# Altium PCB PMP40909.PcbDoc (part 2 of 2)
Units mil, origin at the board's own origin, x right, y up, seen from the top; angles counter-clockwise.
Board outline 3960.53 x 2185.03 mil, 4 copper layers (Top Layer, Signal Layer 1, Signal Layer 2, Bottom Layer), stack 45.434 mil thick; 68 components, 27 nets, 148 pads, 352 vias.
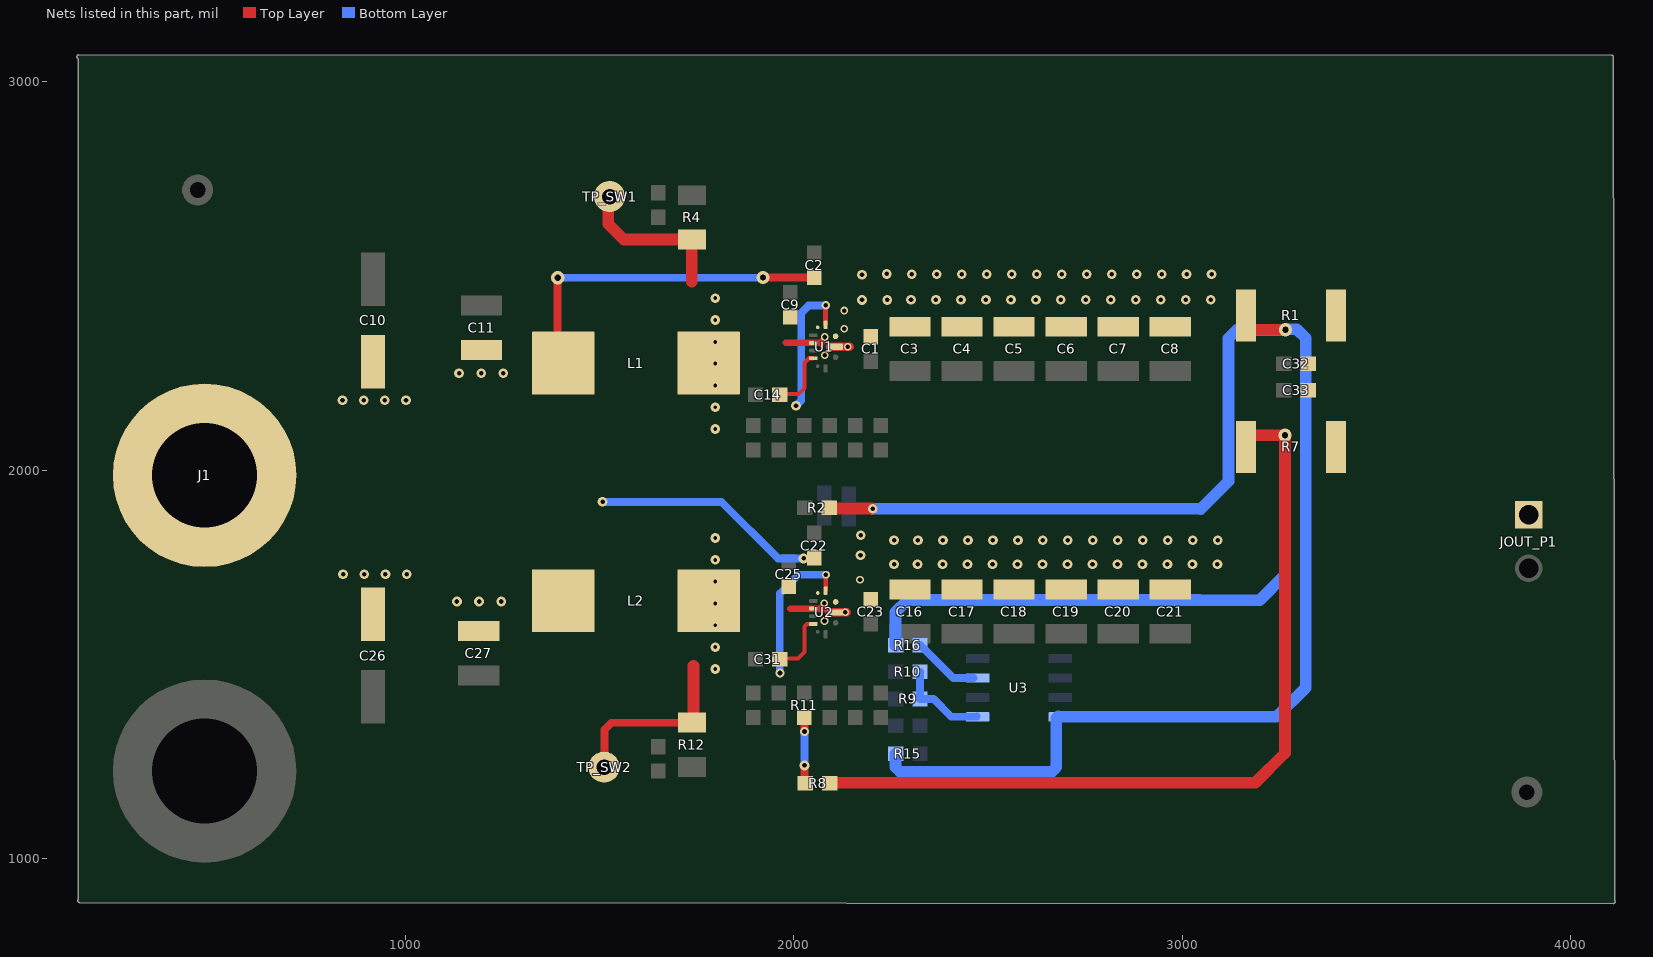
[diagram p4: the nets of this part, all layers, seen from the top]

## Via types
v1: diameter 25, hole 11.81, Top Layer to Bottom Layer, tented both sides, 205 vias
v2: diameter 25, hole 11.81, Top Layer to Bottom Layer, 100 vias
v3: diameter 20, hole 11.81, Top Layer to Bottom Layer, tented both sides, 14 vias
v4: diameter 25, hole 10, Top Layer to Bottom Layer, 14 vias
v5: diameter 20, hole 11.81, Top Layer to Bottom Layer, 4 vias
v6: diameter 23.62, hole 11.81, Top Layer to Bottom Layer, tented both sides, 3 vias
v7: diameter 34, hole 16, Top Layer to Bottom Layer, tented both sides, 3 vias
v8: diameter 34, hole 16, Top Layer to Bottom Layer, 2 vias
v9: diameter 19.68, hole 11.81, Top Layer to Bottom Layer, tented both sides, 2 vias
v10: diameter 23.62, hole 13.78, Top Layer to Bottom Layer, tented both sides, 1 vias
v11: diameter 20, hole 10, Top Layer to Bottom Layer, tented both sides, 1 vias
v12: diameter 20, hole 10, Top Layer to Bottom Layer, 1 vias
v13: diameter 19.68, hole 11.81, Top Layer to Bottom Layer, 1 vias
v14: diameter 22, hole 11.81, Top Layer to Bottom Layer, tented both sides, 1 vias

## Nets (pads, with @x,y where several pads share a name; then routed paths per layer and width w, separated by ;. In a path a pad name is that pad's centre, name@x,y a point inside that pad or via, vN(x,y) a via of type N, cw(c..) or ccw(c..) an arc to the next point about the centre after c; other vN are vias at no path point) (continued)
NetR8_2: R8.2 R11.1 | length 182.7
  Top Layer w15: R11.1@2029,1360.5 R11.1@2030,1361.5
  Top Layer w20: R8.2@2027,1188 2028,1189 v1(2028,1240) v1@2028.5,1239.5 ; v6(2028,1327.5) 2028,1359.5 R11.1@2029,1360.5
  Bottom Layer w15: v1(2028,1240) 2028,1237.5 2027.5,1237 v1@2029,1235.5 ; v6(2028,1327.5) 2028,1328 v6@2029,1329
  Bottom Layer w20: v1(2028,1240) v6(2028,1327.5)
NetR9_2: R9.2 R10.1 U3.1 | length 235.2
  Bottom Layer w20: R10.1@2325.5,1481 R9.2@2325.5,1411.09 2360.32,1411.09 2406.1,1365.3 2470.8,1365.3 U3.1@2471.5,1366
NetR16_2: R16.2 U3.3 | length 172.8
  Bottom Layer w20: R16.2@2325.5,1550 2326,1550 2410.7,1465.3 U3.3@2463.2,1465.3
SW1: C9.1 L1.2 R4.1 TP_SW1.1 U1.4 U1.9 | length 611.4
  Top Layer w5: 2062,2329 2071,2338 ; 2063,2326 2072,2317 ; 2088,2332 U1.4@2097,2323 ; 2089,2305 U1.4@2098,2314
  Top Layer w17: 1979.16,2327.84 U1.9@2050.74,2327.84 2072.16,2327.84
  Top Layer w20: U1.4@2092,2318 U1.4@2106.84,2318
  Top Layer w21: U1.4@2100.34,2318 v9@2144.5,2318
  Top Layer w30: TP_SW1.1@1523,2702 1523,2634 1563.09,2593.91 R4.1@1738,2593.91 1738,2485
  other v3: 2080,2296 2080,2343
  other v4: 1798,2106 1798,2162.17 1798,2218.33 1798,2274.5 1798,2330.67 1798,2386.83 1798,2443
  other v9: 2139,2318
SW2: C25.1 L2.2 R12.1 TP_SW2.1 U2.4 U2.9 | length 673.5
  Top Layer w5: 2062,1645 v3@2071,1654 ; 2063,1642 2072,1633 ; 2088,1648 U2.4@2097,1639 ; 2089,1621 U2.4@2098,1630
  Top Layer w10: R12.1@1730,1360 R12.1@1738,1352
  Top Layer w17: 1991.16,1643.84 U2.9@2050.74,1643.84 2076.84,1643.84
  Top Layer w20: TP_SW2.1@1513,1235 1513,1332 1531.09,1350.09 R12.1@1738,1350.09 ; R12.1@1737.01,1351.08 R12.1@1737.04,1351.04 ; U2.4@2091,1634 U2.4@2106.84,1634
  Top Layer w21: U2.4@2097,1634.5 v3@2137.16,1634.5
  Top Layer w30: R12.1@1742,1357 1742,1497
  other v3: 2079.5,1612 2133,1634.5 2079,1657.5
  other v4: 1798,1488.5 1798,1544.67 1798,1600.83 1798,1657 1798,1713.17 1798,1769.33 1798,1825.5
VCC1: C14.2 U1.6 U1.11 | length 528.4
  Top Layer w10: C14.2@1974,2196 2013,2196 2028,2211 ; U1.6@2082,2374.34 U1.6@2082.24,2374.1 ; v14@2082,2423 v14@2085,2426
  Top Layer w11: 2028,2211 2028,2276.91 2039.57,2288.47 U1.11@2050.74,2288.47
  Top Layer w12: U1.6@2082,2374.34 v14@2082,2423
  Bottom Layer w10: v1(2006,2166) v1@2010.5,2166
  Bottom Layer w20: v1(2006,2166) 2019.5,2179.5 2019.5,2405 2038.5,2424 v14@2084,2424
  other v14: 2083,2424.5
VCC2: C31.2 U2.6 U2.11 | length 537.2
  Top Layer w10: C31.2@1977,1515 2011,1515 2028,1532 2028,1597.94 2034.53,1604.47 U2.11@2050.74,1604.47 ; v3@2082.24,1731.24 v3@2083,1732
  Top Layer w12: U2.6@2082.24,1690.1 v3@2082.24,1731.24
  Bottom Layer w20: v10@1964,1476 1964,1682.5 2012.5,1731 v3(2083,1731)
  other v10: 1965,1478
VIN1: C2.2 C10.1 C11.1 C22.2 C26.1 C27.1 J1.1 L1.1 L2.1 U1.7 U2.7 | length 1409.6
  Top Layer w20: L1.1@1392,2352.5 v7@1392,2493 ; v7(1921.38,2496.38) C2.2@2053,2496.38 ; v1@2026,1772 C22.2@2055,1772
  Bottom Layer w20: v7(1392.5,2495.5) 1920.5,2495.5 v7(1921.38,2496.38) v7@1923.5,2498.5 ; v1@1509.5,1918.5 1814,1918.5 1959.5,1773 v1(2025.5,1773)
  other v1: 1133,1662 1190,1662 1247,1662 840,1732.5 894.5,1732.5 949,1732.5 1003.5,1732.5 1508,1919 838.5,2180 893,2180 947.5,2180 1002,2180 1138.5,2250 1195.5,2250 1252.5,2250
VOUT: C32.1 C33.1 JOUT_P1.1 R1.2 R7.2
VOUT1: C1.1 C3.1 C4.1 C5.1 C6.1 C7.1 C8.1 R1.1 R2.2 R15.1 U1.5 U3.8 | length 3912.7
  Top Layer w20: R1.1@3159,2363 R1.1@3160,2362
  Top Layer w30: R2.2@2088,1901.5 v1@2201,1901.5 ; R1.1@3160,2362 v8(3266,2362)
  Bottom Layer w30: v1(2203.5,1901) 3047.5,1901 3048.25,1900.25 3119.5,1971.5 3119.5,2340 3141.5,2362 v8(3266,2362) ; R15.1@2262,1270 2262,1236 2275,1223 2664,1223 2676.46,1235.46 2676.46,1361.96 U3.8@2679.5,1365 ; U3.8@2681,1366.5 U3.8@2679.5,1365 ; v8@3267,2363 3295.5,2363 3318,2340.5 3318,1440 3243,1365 U3.8@2679.5,1365
  other v2: 2176,2438.5 2241,2438.5 2302,2439 2366.33,2439 2430.67,2439 2495,2439 2559.33,2439 2623.67,2439 2688,2439 2752.33,2439 2816.66,2439 2881,2439 2945.33,2439 3009.66,2439 3074,2439 2176,2503.5 2304,2505 2368.33,2505 2432.67,2505 2497,2505 2561.33,2505 2625.67,2505 2690,2505 2754.33,2505 2818.67,2505 2883,2505 2947.33,2505 3011.67,2505 3076,2505 2240,2505.5
  other v5: 2130,2364.5 2130,2411
VOUT2: C16.2 C17.2 C18.2 C19.2 C20.2 C21.2 C23.1 R7.1 R8.1 R16.1 U2.5 | length 3614.9
  Top Layer w20: R7.1@3159,2089 3159.5,2089.5 3161.5,2089.5 R7.1@3160,2091
  Top Layer w30: R8.1@2090.12,1195 2090.62,1195.5 3188.5,1195.5 3265,1272 v8(3265,2090) 3175,2090 R7.1@3171,2094
  Bottom Layer w30: R16.1@2262,1549 2262,1634 2294,1666 3045,1666 ; 3043,1665.5 3200,1665.5 3265,1730.5 v8(3265,2090)
  other v2: 2258.5,1758 2319,1758 2383.33,1758 2447.67,1758 2512,1758 2576.33,1758 2640.67,1758 2705,1758 2769.33,1758 2833.67,1758 2898,1758 2962.33,1758 3026.67,1758 3091,1758 2172.11,1781 2258.5,1820 2320,1820 2384.33,1820 2448.67,1820 2513,1820 2577.33,1820 2641.67,1820 2706,1820 2770.33,1820 2834.67,1820 2899,1820 2963.33,1820 3027.67,1820 3092,1820 2172.5,1833
  other v5: 2170.8,1718.02
pads on no net: U3.5 U3.6 U3.7

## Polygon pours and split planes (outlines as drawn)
GND on Top Layer "Top Layer-GND" (solid, remove dead copper, pour order 220): 162,3056.5 167,3061.5 4108.5,3061.5 4108.5,891 4107.5,892 162,892 162,3059.25 159.75,3061.5
no net on Top Layer "Top Layer-No Net 1" (solid, remove dead copper, pour order 214): 161,3062.5 166,3067.5 4114,3067.5 4114,890 4109.5,885.5 4107,888 168,888 168,3060.5 158.5,3070
VOUT on Top Layer "TOP_LAYER_VOUT_P180" (solid, remove dead copper, pour order 180): 3293.5,2687 4089,2687 4089,1817 3293.5,1817
VOUT2 on Top Layer "TOP_LAYER_VOUT2_P178" (solid, remove dead copper, pour order 178): 2101,1652 2164.5,1652 2164.5,1633.5 3240,1633.5 3240,2153.5 2255.5,2153.5 2255.5,1874 2101,1874
VOUT1 on Top Layer "TOP_LAYER_VOUT1_P172" (solid, remove dead copper, pour order 172): 2104,3045 2103,3044 2103,2385 2097,2385 2096.5,2384.5 2097,2384 2097,2336.5 2098.5,2335.5 2168,2335.5 2168,2312.5 3234,2312.5 3235,2313.5 3235,3045.5 2103.5,3045.5 2103,3045
SW2 on Top Layer "TOP_LAYER_SW2_P168" (solid, remove dead copper, pour order 168): 1650,1872.5 1650.5,1873 1960.5,1873 1960.5,1729.5 2017,1729.5 2017,1669.5 2034.5,1652 2034.5,1635.5 2026.5,1635.5 2000.5,1609.5 2000.5,1590 2000,1589.5 1881,1589.5 1881,1450.5 1880.5,1451 1649,1451 1649,1873
SW1 on Top Layer "TOP_LAYER_SW1_P166" (solid, remove dead copper, pour order 166): 1645.88,2490 1646.88,2489.5 1874.88,2489.5 1874.88,2471 1875.38,2470.5 1875.88,2471 1965,2471 1965,2429 2016,2429 2016,2351.88 2031.38,2336.5 2031.38,2318.5 1998.88,2286 1998.88,2281.5 1874.88,2281.5 1874.88,2066.5 1874.38,2067 1645.88,2067
VIN1 on Top Layer "TOP_LAYER_VIN1_P144" (solid, remove dead copper, pour order 144): 247.5,2369 248.5,2370 1546.5,2370 1546.5,1513.5 1545,1515 176.5,1515 176.5,2370
GND on Bottom Layer "Bottom Layer-GND" (solid, remove dead copper, pour order 202): 163,3067 167.5,3062.5 4099.5,3062.5 4099.5,903 4109.5,893 156.5,893 158.5,895 158.5,3071
GND on Signal Layer 2 "Signal Layer 2-GND" (solid, remove dead copper, pour order 218): 175.5,3054.5 4102,3054.5 4102,893 4103,892 162,892 162,3057 167.5,3062.5
VOUT on Signal Layer 2 "SIGNAL_LAYER_2_VOUT_P146" (solid, remove dead copper, pour order 146): 3298,2686 4082.5,2686 4082.5,1815.5 3796.5,1815.5 3298,1815.5
VIN1 on Signal Layer 2 "SIGNAL_LAYER_2_VIN1_P142" (solid, remove dead copper, pour order 142): 217,2369 247.5,2369 1546.5,2369 1546.5,1514 1543.5,1511 1540.5,1514 185,1514 185,2367.5
SW1 on Signal Layer 2 "SIGNAL_LAYER_2_SW1_P138" (solid, remove dead copper, pour order 138): 1649,2473 1649.5,2473.5 2097,2473.5 2097,2351 2096.5,2350.5 2107.5,2339.5 2174,2339.5 2175,2338.5 2175,2297 2174.5,2297.5 2107.5,2297.5 2094.5,2284.5 2094.5,2070 1647.5,2070 1648,2070.5 1648,2473.5
VOUT2 on Signal Layer 2 "SIGNAL_LAYER_2_VOUT2_P136" (solid, remove dead copper, pour order 136): 2100.5,1861.5 2234.5,1861.5 2234.5,2153.5 3230.5,2153.5 3230.5,1641 2173,1641 2172,1642 2172,1657.5 2117,1657.5 2100.5,1674 2100.5,1860.5 2101,1861
SW2 on Signal Layer 2 "SIGNAL_LAYER_2_SW2_P140" (solid, remove dead copper, pour order 140): 1649.5,1871 2090,1871 2093,1868 2093,1666 2105,1654 2156,1654 2156,1611 2102,1611 2085,1594 2085,1446 2084.5,1445.5 2082.5,1447.5 1649.5,1447.5
VOUT1 on Signal Layer 2 "SIGNAL_LAYER_2_VOUT1_P134" (solid, pour order 134): 2114.7,3051 3234.5,3051 3234.5,2321.5 3233.5,2320.5 2179,2320.5 2179.5,2321 2179.5,2351.5 2104.5,2351.5 2103,2353 2103.5,2353.5 2103.5,3037
GND on Signal Layer 1 "Signal Layer 1-GND" (solid, pour order 198): 157.5,3066.5 160,3069 4101,3069 4108.5,3061.5 4108.5,902 4101,894.5 162,894.5 162,3056.5

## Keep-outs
Keep-Out Layer:
  text ".Layer_Name" at 577,-858.49 h60

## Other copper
Top Layer:
  rectangle net VOUT2: 2066.5,1175.5 2074.5,1212.5
  rectangle net VOUT1: 2065.5,1884.5 2072,1921.5
  rectangle net AGND2: 2204,1258.5 2245.5,1381.5
  rectangle net VCC2: 1932.5,1453.5 2033,1534.5
  rectangle net VCC1: 1940.5,2142.5 2035,2227.5
  rectangle net VIN1: 2041,2369 2066,2507
  rectangle net VIN1: 2041,1680 2067,1774
  rectangle net SW1: 2068,2284 2091,2356
  rectangle net AGND2: 2073,1287 2114,1383.5
  rectangle net AGND2: 1982,1258.5 2216,1309.5
  rectangle net AGND2: 1940.5,1258.5 1985.5,1383.5
  rectangle net FB2: 2039.5,1401.5 2067.5,1587
  rectangle net AGND2: 1919,1540.5 2017,1578
  rectangle net AGND2: 1877,1414.5 1926.5,1578
  rectangle net AGND1: 2201.5,1959.5 2243,2065
  rectangle net AGND1: 2069.5,1993 2113.5,2072
  rectangle net AGND1: 1983,1959 2217,2002
  rectangle net AGND1: 1942,1959 1992.5,2072
  rectangle net FB1: 2041,2095 2067,2271
  rectangle net AGND1: 1927,2235 2015,2271
  rectangle net AGND1: 1877.5,2106 1934,2271
  rectangle net SW2: 2068,1600 2091,1672
Bottom Layer:
  rectangle net VOUT2: 2243,1517 2282.5,1526
  rectangle net NetR16_2: 2306,1517.5 2345,1532
  rectangle net NetR16_2: 2300,1517.5 2307,1568
  rectangle net VOUT2: 2243,1525.5 2282.5,1532.5
  text ".Layer_Name" at 577,-858.49 h60

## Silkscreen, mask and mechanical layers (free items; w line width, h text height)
Top Overlay:
  text "PMP40909" at 2463.5,2836.5 h60
  text "GND" at 428.5,2605.5 h30
  text "VIN" at 405.5,2297.5 h50
  text "VOUT" at 3797,2017.5 h50
  text "GND" at 3826,1577 h50
  text "GND" at 423,1511.5 h50
  text "GND" at 3971,1144.5 h30
Top Paste:
  text ".Layer_Name" at 577,-858.49 h60
Bottom Paste:
  text ".Layer_Name" at 577,-858.49 h60
Top Solder:
  text ".Layer_Name" at 577,-858.49 h60
  text ".Layer_Name" at 577,-858.49 h60
Bottom Solder:
  text ".Layer_Name" at 577,-858.49 h60
Drill Guide:
  text ".Layer_Name" at 577,-858.49 h60
M1 Board Outline:
  lines w10: 159.5,3064.5 4105.5,3064 ; 162,892 4110,889.5 ; 162.5,897 162.5,3059 ; 4105.5,3063.5 4109.32,892
  text ".Layer_Name" at 577,-858.49 h60
M2 Board Dimensions:
  rectangle: 0,-275 125,-150
  rectangle: 125,-400 500,-275
  lines w7: 0,-275 1000,-275 ; 125,-400 125,-150 ; 250,-400 250,-150 ; 500,-400 500,-150 ; 750,-400 750,-150 ; 0,-400 1000,-400 1000,-150 0,-150 0,-400
  text ".Layer_Name" at 577,-858.49 h60
M3 3D STEP Top:
  text ".Layer_Name" at 577,-858.49 h60
M5 Assembly Top:
  lines w10: -292,-930.17 6308,-930.17 ; -292,-726.83 6310,-726.83 ; -292,-523.5 -292,-1133.5 3713,-1133.5 6310,-1133.5 6310,-523.5 -291.5,-523.5 -291.5,-1133.5 1284,-1133.5 ; 2173,-1133.5 2173,-523.5 ; 3440,-726.83 3440,-523.5 ; 4280,-726.83 4280,-523.5 ; 4902,-1140 4902,-937.17
  text "COMPONENTS MARKED 'DNP' SHOULD NOT BE POPULATED." at 1153.5,-318.5 h60
  text "ASSEMBLY VARIANT:" at 1153,-434 h60
  text ".VariantName" at 2189,-434 h60
  text "PCB VIEWED FROM TOP SIDE" at -228.5,-655.67 h60
  text "BOARD #:" at 2248,-655.67 h60
  text ".PRJ_Number" at 2793.5,-655.67 h60
  text "REV:" at 3638,-655.67 h60
  text ".PCB_Rev" at 3929.5,-655.67 h60
  text "SVN REV:" at 4476,-655.67 h60
  text ".VersionControl_RevNumber" at 4982,-655.67 h60
  text "TID #:" at 2248,-859 h60
  text ".TID" at 2793.5,-859 h60
  text "PLOT NAME =" at -228.5,-1064.34 h60
  text ".plot_File_Name" at 577,-1064.34 h60
  text "GENERATED    :" at 2250,-1064.34 h60
  text ".Print_Date" at 3119.5,-1064.34 h60
  text ".Print_Time" at 3848.5,-1064.34 h60
  text "TEXAS INSTRUMENTS" at 5113,-1064.34 h60
M6 Assembly Bottom:
  lines w10: -292.5,-727.33 6309.5,-727.33 ; -290.5,-930.67 6309.5,-930.67 ; 1115.5,-1140.5 1115.5,-937.67 ; 1737.5,-727.33 1737.5,-524 ; 2577.5,-727.33 2577.5,-524 ; 3844.5,-1134 3844.5,-524 ; 4733.5,-1134 6309,-1134 6309,-524 -292.5,-524 -292.5,-1134 2304.5,-1134 6309.5,-1134 6309.5,-524
  text "COMPONENTS MARKED 'DNP' SHOULD NOT BE POPULATED." at 6102,-318 h60
  text ".VariantName" at 5058,-434 h60
  text "ASSEMBLY VARIANT:" at 6097,-434 h60
  text ".VersionControl_RevNumber" at 1035.5,-656.17 h60
  text "SVN REV:" at 1541.5,-656.17 h60
  text ".PCB_Rev" at 2088,-656.17 h60
  text "REV:" at 2379.5,-656.17 h60
  text ".PRJ_Number" at 3224,-656.17 h60
  text "BOARD #:" at 3769.5,-656.17 h60
  text "PCB VIEWED FROM BOTTOM SIDE" at 6246,-656.17 h60
  text ".TID" at 3224,-859.5 h60
  text "TID #:" at 3769.5,-859.5 h60
  text "TEXAS INSTRUMENTS" at 904.5,-1064.84 h60
  text ".Print_Time" at 2169,-1064.84 h60
  text ".Print_Date" at 2898,-1064.84 h60
  text "GENERATED    :" at 3767.5,-1064.84 h60
  text ".plot_File_Name" at 5440.5,-1064.84 h60
  text "PLOT NAME =" at 6246,-1064.84 h60
M9 Title Sheet:
  drawing of 57 lines, arcs and shapes, not listed
  text "1" at 739.84,8036.5 h70
  text "2" at 3235.5,8036.5 h70
  text "3" at 5724.84,8036.5 h70
  text "4" at 8231.51,8036.5 h70
  text "5" at 10730.5,8036.5 h70
  text "6" at 13235.5,8036.5 h70
  text "A" at -416.5,6893.5 h70
  text "A" at 14383.5,6893.5 h70
  text "B" at -416.5,4513.5 h70
  text "B" at 14383.5,4513.5 h70
  text "C" at -416.5,2138.5 h70
  text "C" at 14383.5,2138.5 h70
  text "PROJECT TITLE:" at 11343.5,277.5 h45
  text ".PRJ_Title" at 11393.5,144.17 h70
  text "DESIGNED FOR:" at 11343.5,-23.5 h45
  text ".PRJ_Customer" at 11393.5,-163.5 h70
  text "D" at -416.5,-231.5 h70
  text "D" at 14383.5,-231.5 h70
  text "FILE NAME:" at 11343.5,-323.5 h45
  text ".PCB_File_Name_No_Path" at 11393.5,-443.5 h70
  text "Texas Instruments (TI) and/or its licensors do not warrant the accuracy or completeness of this specification" at 6374,-605.34 h45
  text "ENGINEER:" at 11343.5,-613.5 h45
  text "LAYOUT BY:" at 12848.5,-613.5 h45
  text "or any information contained therein. TI and/or its licensors do not warrant that this design will meet" at 6329.01,-718 h45
  text ".PRJ_Engineer" at 11393.5,-768.49 h70
  text ".PCB_Layout" at 12899,-768.49 h70
  text "the specifications, will be suitable for your application or fit for any particular purpose, or will operate in" at 6329.01,-830.67 h45
  text ".Layer_Name" at 577,-858.49 h60
  text "ALTIUM DESIGNER VERSION:" at 12848.5,-923.5 h45
  text "an implementation. TI and/or its licensors do not warrant that the design is production worthy. You should" at 6329.01,-943.33 h45
  text "completely validate and test your design implementation to confirm the system functionality for your application." at 6374,-1056 h45
  text ".print_Scale" at 11393.5,-1056.83 h70
  text ".Application_BuildNumber" at 12899,-1056.83 h70
  text "1" at 739.84,-1263.5 h70
  text "2" at 3235.5,-1263.5 h70
  text "3" at 5724.84,-1263.5 h70
  text "4" at 8231.51,-1263.5 h70
  text "5" at 10730.5,-1263.5 h70
  text "6" at 13235.5,-1263.5 h70
M10 Fab Notes:
  drawing of 189 lines, arcs and shapes, not listed
  text "DESIGN INFORMATION" at 12382.02,6356.17 h60
  text "MIN. TRACK WIDTH:" at 11737.46,6224.05 h60
  text "8" at 12833.7,6224.05 h60
  text "MIL" at 12988.46,6224.05 h60
  text "MIN. CLEARANCE:" at 11737.46,6099.92 h60
  text "0.2" at 12773.7,6099.93 h60
  text "mm" at 12988.46,6099.92 h60
  text "MIN. VIA PAD SIZE:" at 11737.46,5975.8 h60
  text "24" at 12803.71,5975.8 h60
  text "MIL" at 12988.46,5975.8 h60
  text "0.05mm (2MIL)" at 12432.46,5845.9 h60
  text "MINIMUM ANNULAR RING" at 11408.23,5837.67 h60
  text "EXTERNAL" at 13140.46,5837.67 h60
  text "PER" at 11608.23,5727.55 h60
  text "IPC-D-275 CLASS 2 LEVEL C" at 11828.23,5727.54 h60
  text "MIL, HOLES" at 13316.46,5627.07 h60
  text "+/-" at 12924,5618.48 h60
  text "+/-" at 13778,5618.48 h60
  text "REGISTRATION TOLERANCES:" at 11408.23,5617.42 h60
  text "METAL" at 12608,5617.42 h60
  text "5" at 13184.2,5617.42 h60
  text "3" at 14017.2,5617.42 h60
  text "MIL" at 14133.46,5617.42 h60
  text "HOLE SIZE TOLERANCE (UNLESS OTHERWISE SPECIFIED):" at 11408.23,5519.1 h60
  text "+/-" at 13778,5516.23 h60
  text "3" at 14017.2,5515.17 h60
  text "MIL" at 14133.46,5515.17 h60
  text "MATERIAL:" at 11333.46,5377.52 h60
  text "FR-4 High Tg" at 12319.9,5249 h60
  text "X" at 12175.46,5241.01 h60
  text "FR-408" at 11754.46,5236.49 h60
  text "OTHER" at 13242.46,5236.49 h60
  text "62 MIL (1.6mm) +/-10%" at 12074.56,5093.46 h60
  text "X" at 11954.46,5091.01 h60
  text "THICKNESS:" at 11408.23,5085.24 h60
  text "OTHER" at 13359.46,5085.24 h60
  text "TOLERANCE:" at 11408.23,4946.92 h60
  text "X" at 12256.46,4946.92 h60
  text "ANSI IPC-6012 TYPE 3 CLASS 2" at 12434.48,4946.92 h60
  text "OTHER +/-" at 12434.46,4802.73 h60
  text "BOW & TWIST:" at 11408.23,4657.54 h60
  text "X" at 12256.46,4657.54 h60
  text "ANSI IPC-6012 TYPE 3 CLASS 2" at 12434.48,4657.54 h60
  text "OTHER +/-" at 12434.46,4510.85 h60
  text "DRILLING:" at 11333.46,4380.23 h60
  text "NC_DRILL FILES" at 13094.46,4275.04 h60
  text "REFERENCE:" at 11408.23,4271.1 h60
  text "X" at 12065.46,4271.01 h60
  text "AS SHOWN" at 12243.46,4271.1 h60
  text "X" at 12966.46,4271.1 h60
  text "OTHER" at 13392.46,4128.85 h60
  text "PTH COPPER THICKNESS:" at 11407.91,4125.32 h60
  text "X" at 12547.14,4125.32 h60
  text "20-30 um" at 12675.14,4125.32 h60
  text "BOARD FINISH:" at 11333.46,3977.73 h60
  text "SILKSCREEN:" at 11488.68,3867.6 h60
  text "X" at 12446.46,3867.6 h60
  text "TOP" at 12563.46,3867.6 h60
  text "X" at 12956.46,3867.6 h60
  text "BOTTOM" at 13074.46,3867.6 h60
  text "SILKSCREEN COLOR:" at 11488.68,3712.41 h60
  text "X" at 12445.46,3712.41 h60
  text "WHITE" at 12563.46,3712.41 h60
  text "OTHER" at 13074.46,3712.41 h60
  text "X" at 12576.46,3568.96 h60
  text "GREEN" at 12694.46,3568.96 h60
  text "OTHER" at 13312.46,3568.96 h60
  text "SOLDER RESIST COLOR:" at 11488.68,3562.1 h60
  text "X" at 12576.46,3414.71 h60
  text "MATTE" at 12694.46,3414.71 h60
  text "SEMI-GLOSS" at 13312,3414.07 h60
  text "IMMERSION GOLD (ENIG)" at 12394.46,3241.94 h60
  text "ENEPIG" at 13732,3234.72 h60
  text "SURFACE FINISH:" at 11333.46,3233.72 h60
  text "X" at 12216.46,3233.72 h60
  text "IMM. TIN/SILVER OR EQUIV" at 11663,3096.4 h60
  text "OTHER" at 13094.46,3092.47 h60
  text "ARRAY/PANEL:" at 11333.46,2937.09 h60
  text "CUT AND TRIM PER M1 BOARD OUTLINE" at 12394.46,2928.87 h60
  text "N.C. ROUTE" at 12394.46,2792.9 h60
  text "X" at 13082.46,2792.9 h60
  text "V. SCORE" at 13260.46,2792.9 h60
  text "CERTIFICATION:" at 11333.46,2663.77 h60
  text "MATERIALS AND WORKMANSHIP FOR ALL PCBS" at 12058.46,2663.77 h60
  text "TO MEET OR EXCEED THE REQUIREMENTS OF:" at 12058.46,2569.71 h60
  text "X" at 11695.97,2441.08 h60
  text "ANSI IPC-A-600F CLASS ->" at 11823.96,2441.08 h60
  text "X" at 13471.97,2441.08 h60
  text "2" at 13581.96,2441.08 h60
  text "1" at 13266.96,2439.58 h60
  text "3" at 13935.96,2439.58 h60
  text "X" at 12507.97,2293.39 h60
  text "RoHS" at 12635.96,2293.39 h60
  text "OTHER" at 13280.36,2293.39 h60
  text "PER ORDER" at 13677.42,2293.39 h60
  text "ALL BOARDS MUST MEET OR EXCEED UL94-V0 REQUIREMENTS." at 11361,2139.57 h60
  text "PCB MUST BEAR THE UL94V-0 UL REGISTERED MATERIAL ID NUMBER" at 11361,2023.5 h60
  text "ADDITIONAL REQUIREMENTS:" at 11333.46,1854.08 h60
  text "MICROSECTION:" at 11408.23,1746.95 h60
  text "YES" at 12313.96,1746.95 h60
  text "REQUIRED" at 13175.46,1602.62 h60
  text "BARE BOARD ELEC. TEST:" at 11408.23,1599.76 h60
  text "NONE" at 12713.96,1599.76 h60
  text "X" at 13057.46,1599.76 h60
  text "PER ORDER" at 13767.46,1599.76 h60
  text "XX MIL VIAS REQUIRE NON-CONDUCTIVE FILL AND PLANARIZE" at 11576.38,1394.82 h59
  text "XX MIL VIAS REQUIRE CONDUCTIVE FILL AND PLANARIZE" at 11584.38,1290.84 h60
  text "OUTER XX MIL TRACES REQUIRE 50 OHM SINGLE-ENDED IMPEDANCE" at 11583.39,1127.46 h58
  text "LAYER 2 & 3 (INNER LAYERS) XX MIL WIDE, XX MIL SPACE / TRACES REQUIRE 100 OHM DIFFERENTIAL IMPEDANCE" at 11575.39,891.74 h60
  text ".Layer_Name" at 577,-858.49 h60
M11 Gerber Information:
  lines w10: -292,-930.17 6308,-930.17 ; -292,-726.83 6310,-726.83 ; -292,-523.5 -292,-1133.5 3713,-1133.5 6310,-1133.5 6310,-523.5 -291.5,-523.5 -291.5,-1133.5 1284,-1133.5 ; 2173,-1133.5 2173,-523.5 ; 3440,-726.83 3440,-523.5 ; 4280,-726.83 4280,-523.5 ; 4902,-1140 4902,-937.17
  text "ALL ARTWORK VIEWED FROM TOP SIDE" at -228.5,-655.67 h60
  text "BOARD #:" at 2248,-655.67 h60
  text ".PRJ_Number" at 2793.5,-655.67 h60
  text "REV:" at 3638,-655.67 h60
  text ".PCB_Rev" at 3929.5,-655.67 h60
  text "SVN REV:" at 4476,-655.67 h60
  text ".VersionControl_RevNumber" at 4982,-655.67 h60
  text "LAYER NAME =" at -228.5,-858.49 h60
  text "TID #:" at 2248,-859 h60
  text ".TID" at 2793.5,-859 h60
  text "PLOT NAME =" at -228.5,-1064.34 h60
  text ".plot_File_Name" at 577,-1064.34 h60
  text "GENERATED    :" at 2250,-1064.34 h60
  text ".Print_Date" at 3119.5,-1064.34 h60
  text ".Print_Time" at 3848.5,-1064.34 h60
  text "TEXAS INSTRUMENTS" at 5113,-1064.34 h60
M12 Stackup:
  drawing of 295 lines, arcs and shapes, not listed
  text "Layer" at 9821.59,7694.94 h60
  text "Name" at 10231.51,7694.94 h60
  text "Material" at 11171.25,7694.94 h60
  text "Thickness" at 12031.02,7694.94 h60
  text "Constant" at 12680.85,7694.94 h60
  text "Board Layer Stack" at 13250.71,7694.94 h60
  text "Top Overlay" at 10231.51,7574.94 h60
  text "Top Solder" at 10231.51,7454.94 h60
  text "Solder Resist" at 11171.25,7454.94 h60
  text "0.40mil" at 12031.02,7454.94 h60
  text "3.5" at 12680.85,7454.94 h60
  text "1" at 9821.59,7334.94 h60
  text "Top Layer" at 10231.51,7334.94 h60
  text "2.80mil" at 12031.02,7334.94 h60
  text "Dielectric1" at 10231.51,7214.94 h60
  text "FR-4" at 11171.25,7214.94 h60
  text "13.00mil" at 12031.02,7214.94 h60
  text "4.8" at 12680.85,7214.94 h60
  text "2" at 9821.59,7094.94 h60
  text "Signal Layer 1" at 10231.51,7094.94 h60
  text "1.42mil" at 12031.02,7094.94 h60
  text "Dielectric 2" at 10231.51,6974.94 h60
  text "FR-4" at 11171.25,6974.94 h60
  text "11.00mil" at 12031.02,6974.94 h60
  text "4.2" at 12680.85,6974.94 h60
  text "3" at 9821.59,6854.94 h60
  text "Signal Layer 2" at 10231.51,6854.94 h60
  text "1.42mil" at 12031.02,6854.94 h60
  text "Dielectric 3" at 10231.51,6734.94 h60
  text "FR-4" at 11171.25,6734.94 h60
  text "13.00mil" at 12031.02,6734.94 h60
  text "4.2" at 12680.85,6734.94 h60
  text "4" at 9821.59,6614.94 h60
  text "Bottom Layer" at 10231.51,6614.94 h60
  text "2.80mil" at 12031.02,6614.94 h60
  text "Bottom Solder" at 10231.51,6494.94 h60
  text "Solder Resist" at 11171.25,6494.94 h60
  text "0.40mil" at 12031.02,6494.94 h60
  text "3.5" at 12680.85,6494.94 h60
  text "Bottom Overlay" at 10231.51,6374.94 h60
  text ".Layer_Name" at 577,-858.49 h60
M14 Component Bodies Bottom:
  text ".Layer_Name" at 577,-858.49 h60
M15 Courtyards Top:
  text ".Layer_Name" at 577,-858.49 h60
M16 Courtyards Bottom:
  text ".Layer_Name" at 577,-858.49 h60
Drill Drawing:
  circle w10: c5363.72,3089.64 r27.63
  lines w10: 5336.09,2592.36 5363.72,2564.74 5391.34,2592.36 5363.72,2619.99 5336.09,2592.36 ; 5336.09,2689.06 5391.34,2689.06 5391.34,2744.31 5336.09,2744.31 5336.09,2689.06 ; 5336.09,2868.63 5391.34,2868.63 5363.72,2813.38 5336.09,2868.63 ; 5336.09,2951.51 5349.9,2951.51 5363.72,2937.7 5377.53,2951.51 5391.34,2951.51 5377.53,2965.32 5391.34,2979.14 5377.53,2979.14 5363.72,2992.95 5349.9,2979.14 5336.09,2979.14 5349.9,2965.32 5336.09,2951.51 ; 5336.09,3186.34 5363.72,3200.15 5391.34,3186.34 5377.53,3213.96 5391.34,3241.59 5363.72,3227.78 5336.09,3241.59 5349.9,3213.96 5336.09,3186.34 ; 5336.09,3324.47 5349.9,3324.47 5349.9,3310.66 5377.53,3310.66 5377.53,3324.47 5391.34,3324.47 5391.34,3352.1 5377.53,3352.1 5377.53,3365.91 5349.9,3365.91 5349.9,3352.1 5336.09,3352.1 5336.09,3324.47 ; 5347.14,2700.11 5380.29,2700.11 5380.29,2733.26 5347.14,2733.26 5347.14,2700.11
  lines w12: 5286,2527.44 8517.49,2527.44 ; 5286,3397.68 8517.49,3397.68 ; 5623.86,2403.12 5623.86,3522 ; 5955.86,2403.12 5955.86,3522 ; 6592.43,2403.12 6592.43,3522 ; 6851.57,2403.12 6851.57,3522 ; 7226.72,2403.12 7226.72,3522 ; 7951.05,2403.12 7951.05,3522 ; 5286,2403.12 8517.49,2403.12 8517.49,3522 5286,3522 5286,2403.12
  text "Symbol" at 5360.59,3434.98 h72
  text "Quantity" at 5661.16,3434.98 h72
  text "Finished Hole Size" at 5993.16,3434.98 h72
  text "Plated" at 6629.72,3434.98 h72
  text "Hole Type" at 6888.86,3434.98 h72
  text "Drill Layer Pair" at 7264.02,3434.98 h72
  text "Hole Tolerance" at 7988.35,3434.98 h72
  text "16" at 5661.16,3310.66 h60
  text "10.00mil (0.254mm)" at 5993.16,3310.66 h60
  text "PTH" at 6629.72,3310.66 h60
  text "Round" at 6888.86,3310.66 h60
  text "Top Layer - Bottom Layer" at 7264.02,3310.66 h60
  text "330" at 5661.16,3186.34 h60
  text "11.81mil (0.300mm)" at 5993.16,3186.34 h60
  text "PTH" at 6629.72,3186.34 h60
  text "Round" at 6888.86,3186.34 h60
  text "Top Layer - Bottom Layer" at 7264.02,3186.34 h60
  text "1" at 5661.16,3062.02 h60
  text "13.78mil (0.350mm)" at 5993.16,3062.02 h60
  text "PTH" at 6629.72,3062.02 h60
  text "Round" at 6888.86,3062.02 h60
  text "Top Layer - Bottom Layer" at 7264.02,3062.02 h60
  text "5" at 5661.16,2937.7 h60
  text "16.00mil (0.406mm)" at 5993.16,2937.7 h60
  text "PTH" at 6629.72,2937.7 h60
  text "Round" at 6888.86,2937.7 h60
  text "Top Layer - Bottom Layer" at 7264.02,2937.7 h60
  text "4" at 5661.16,2813.38 h60
  text "40.00mil (1.016mm)" at 5993.16,2813.38 h60
  text "PTH" at 6629.72,2813.38 h60
  text "Round" at 6888.86,2813.38 h60
  text "Top Layer - Bottom Layer" at 7264.02,2813.38 h60
  text "2" at 5661.16,2689.06 h60
  text "51.18mil (1.300mm)" at 5993.16,2689.06 h60
  text "PTH" at 6629.72,2689.06 h60
  text "Round" at 6888.86,2689.06 h60
  text "Top Layer - Bottom Layer" at 7264.02,2689.06 h60
  text "2" at 5661.16,2564.74 h60
  text "270.00mil (6.858mm)" at 5993.16,2564.74 h60
  text "PTH" at 6629.72,2564.74 h60
  text "Round" at 6888.86,2564.74 h60
  text "Top Layer - Bottom Layer" at 7264.02,2564.74 h60
  text "360 Total" at 5661.16,2440.42 h60
M17 Embedded Cavity:
  text ".Layer_Name" at 577,-858.49 h60
M18 Embedded Assembly:
  text ".Layer_Name" at 577,-858.49 h60
M19 Embedded Keepout:
  text ".Layer_Name" at 577,-858.49 h60

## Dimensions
0,-400 to 1000,-400 on M2 Board Dimensions
-13,892.5 to 157.56,3059.87 on M2 Board Dimensions
4108,872.5 to 157.49,3059 on M2 Board Dimensions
